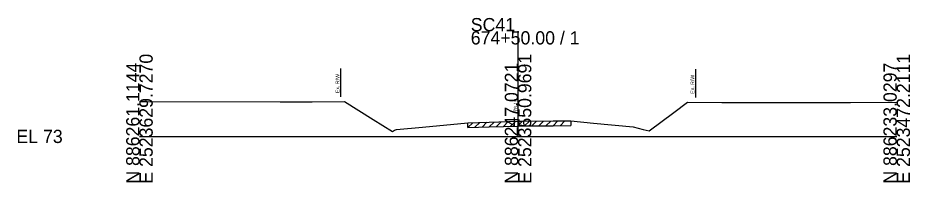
# Model space of a CAD drawing. Extents: x -26 to 183, y -10 to 24021.
# Drawn here: x -25.7 to 162.8, y 6990.3 to 7025.1 of the extents above; entities that cross this region are included whole.
import ezdxf

# ---------------------------------------------------------------- set-up
doc = ezdxf.new("R2010")
doc.units = 0
for name, color, linetype in [('RD_GPK_XS_Cell', 7, 'Continuous'), ('RD_XS_ExGround', 7, 'Continuous'), ('RD_XS_ExPaveRet', 7, 'Continuous'), ('RD_XS_ExRW', 7, 'Continuous'), ('RD_XS_TX_Elev_EX', 7, 'Continuous')]:
    doc.layers.add(name, color=color, linetype=linetype)

msp = doc.modelspace()

# ---------------------------------------------------------------- linework, layer by layer
at = {"layer": 'RD_GPK_XS_Cell'}
for p, q in [((80, 7000), (80, 7022.26)), ((0, 7000), (80, 7000)), ((80, 7000), (160, 7000))]:
    msp.add_line(p, q, dxfattribs=at)
at = {"layer": 'RD_XS_ExGround'}
for p, q in [((0, 7007.42), (1.34, 7007.42)), ((1.34, 7007.42), (29.76, 7007.31)), ((29.76, 7007.31), (36.52, 7007.35)), ((36.52, 7007.35), (43.34, 7007.39)), ((43.34, 7007.39), (49.37, 7003.61)), ((112.92, 7005.09), (115.8, 7007.23)), ((115.8, 7007.23), (123.05, 7007.17)), ((123.05, 7007.17), (132.7, 7007.21)), ((132.7, 7007.21), (150.25, 7007.19)), ((150.25, 7007.19), (160, 7007.23)), ((107.67, 7001.19), (112.92, 7005.09)), ((49.37, 7003.61), (53.5, 7001.04)), ((59.77, 7001.98), (69.39, 7002.87)), ((69.39, 7002.87), (73.86, 7003.01)), ((73.86, 7003.01), (80, 7003.19)), ((80, 7003.19), (80.92, 7003.22)), ((80.92, 7003.22), (87.38, 7003.26)), ((87.38, 7003.26), (91.15, 7003.28)), ((91.15, 7003.28), (95.96, 7002.82)), ((95.96, 7002.82), (104.3, 7001.99)), ((53.5, 7001.04), (53.92, 7001.29)), ((53.92, 7001.29), (54.3, 7001.47)), ((54.3, 7001.47), (59.77, 7001.98)), ((104.3, 7001.99), (106.4, 7001.47)), ((106.4, 7001.47), (107.67, 7001.19))]:
    msp.add_line(p, q, dxfattribs=at)
at = {"layer": 'RD_XS_ExPaveRet'}
for p, q in [((69.39, 7001.87), (70.42, 7002.9)), ((69.39, 7001.87), (69.39, 7002.87)), ((70.89, 7001.92), (71.92, 7002.95)), ((72.39, 7001.96), (73.42, 7002.99)), ((73.86, 7002.01), (80, 7002.19)), ((73.89, 7002.01), (74.92, 7003.04)), ((75.39, 7002.05), (76.42, 7003.08)), ((76.89, 7002.1), (77.92, 7003.13)), ((78.39, 7002.14), (79.42, 7003.17)), ((79.89, 7002.18), (80.92, 7003.22)), ((80, 7002.19), (80.92, 7002.22)), ((80.92, 7002.22), (87.38, 7002.26)), ((81.39, 7002.22), (82.39, 7003.23)), ((82.89, 7002.23), (83.89, 7003.24)), ((84.39, 7002.24), (85.39, 7003.25)), ((85.89, 7002.25), (86.89, 7003.25)), ((87.38, 7002.26), (91.15, 7002.28)), ((87.39, 7002.26), (88.39, 7003.26)), ((88.89, 7002.27), (89.89, 7003.27)), ((91.15, 7003.28), (91.15, 7002.28)), ((69.39, 7001.87), (73.86, 7002.01))]:
    msp.add_line(p, q, dxfattribs=at)
at = {"layer": 'RD_XS_ExRW'}
for p, q in [((42.5, 7014.38), (42.5, 7008.38)), ((117.5, 7014.21), (117.5, 7008.21))]:
    msp.add_line(p, q, dxfattribs=at)

# ---------------------------------------------------------------- texts
at = {"layer": 'RD_GPK_XS_Cell'}
for s, p in [('SC41', (70, 7022.26)), ('674+50.00 / 1', (70, 7019.46)), ('EL 73', (-26, 6998.6))]:
    msp.add_text(s, height=2.8, dxfattribs=at).set_placement(p)
for s, p in [('E 2523629.7270', (2.8, 6990)), ('E 2523550.9691', (82.8, 6990)), ('E 2523472.2111', (162.8, 6990)), ('N 886261.1144', (0, 6990)), ('N 886247.0721', (80, 6990)), ('N 886233.0297', (160, 6990))]:
    msp.add_text(s, height=2.8, rotation=90, dxfattribs=at).set_placement(p)
at = {"layer": 'RD_XS_ExRW'}
for p in [(42.25, 7009.17), (117.25, 7009)]:
    msp.add_text('Ex. R/W ', height=0.8, rotation=90, dxfattribs=at).set_placement(p)
at = {"layer": 'RD_XS_TX_Elev_EX'}
msp.add_text('76.19', height=0.8, rotation=90, dxfattribs=at).set_placement((79.9, 7005.19))

doc.saveas('drawing.dxf')
